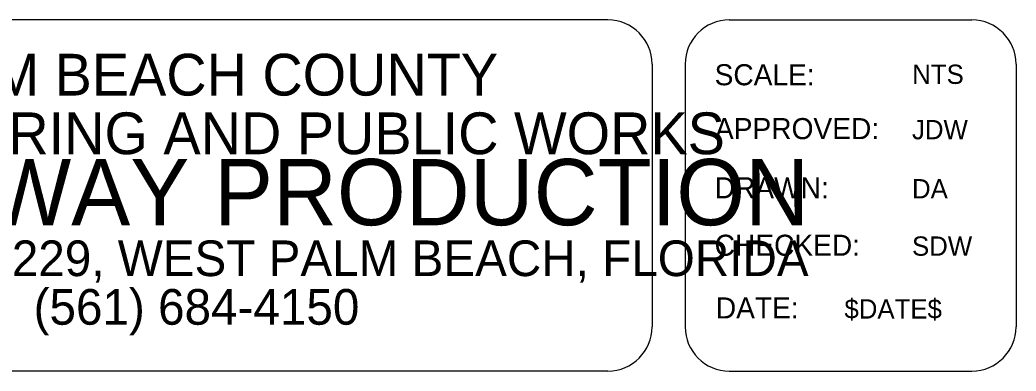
# Model space of a CAD drawing. Extents: x -1.6 to 33.4, y -12.7 to 10.9.
# Drawn here: x 27.968 to 29.959, y -12.676 to -11.974 of the extents above; entities that cross this region are included whole.
import ezdxf

# ---------------------------------------------------------------- set-up
doc = ezdxf.new("R2010")
doc.units = 0
doc.layers.add('Default', color=7, linetype='Continuous')
doc.layers.add('NonPlottingEle_dp', color=7, linetype='Continuous')

msp = doc.modelspace()

# ---------------------------------------------------------------- linework, layer by layer
at = {"layer": 'Default'}
for p, q in [((29.1435, -11.9742), (26.7175, -11.9742)), ((29.386, -11.9742), (29.8712, -11.9742)), ((29.2317, -12.0624), (29.2317, -12.5873)), ((29.2978, -12.0624), (29.2978, -12.5873)), ((29.9595, -12.0624), (29.9595, -12.5873)), ((29.1435, -12.6756), (26.7175, -12.6756)), ((29.386, -12.6756), (29.8712, -12.6756))]:
    msp.add_line(p, q, dxfattribs=at)
for centre, major_axis, start_param, end_param in [((29.1435, -12.0624), (0, 0.0882), 4.712389, 6.283185), ((29.386, -12.0624), (0, 0.0882), 0, 1.570796), ((29.8712, -12.0624), (0, 0.0882), 4.712389, 6.283185), ((29.1435, -12.5873), (0, 0.0882), 3.141593, 4.712389), ((29.386, -12.5873), (0, -0.0882), 4.712389, 6.283185), ((29.8712, -12.5873), (0, -0.0882), 0, 1.570796)]:
    msp.add_ellipse(centre, major_axis=major_axis, ratio=0.999927, start_param=start_param, end_param=end_param, dxfattribs=at)

# ---------------------------------------------------------------- texts
for s, height, p in [('PALM BEACH COUNTY', 0.083446, (27.7023, -12.1253)), ('ENGINEERING AND PUBLIC WORKS', 0.083468, (27.4423, -12.2424)), ('ROADWAY PRODUCTION', 0.132369, (27.3919, -12.3843)), ('P.O. BOX 21229, WEST PALM BEACH, FLORIDA', 0.071224, (27.4011, -12.4859)), ('(561) 684-4150', 0.071224, (27.9952, -12.583))]:
    msp.add_text(s, height=height, rotation=360, dxfattribs=at).set_placement(p)
for s, height, p in [('SCALE:', 0.04207, (29.3567, -12.1047)), ('APPROVED:', 0.04207, (29.3574, -12.2123)), ('JDW', 0.03855, (29.7514, -12.2126)), ('DRAWN:', 0.04207, (29.3568, -12.3305)), ('DA ', 0.03855, (29.7514, -12.3306)), ('CHECKED:', 0.04207, (29.3568, -12.4453)), ('SDW', 0.03855, (29.7514, -12.4452)), ('DATE:', 0.04207, (29.3592, -12.5705)), ('$DATE$', 0.03855, (29.6163, -12.5707))]:
    msp.add_text(s, height=height, dxfattribs=at).set_placement(p)
at = {"layer": 'NonPlottingEle_dp'}
msp.add_text('NTS', height=0.03855, dxfattribs=at).set_placement((29.7518, -12.102))

doc.saveas('drawing.dxf')
